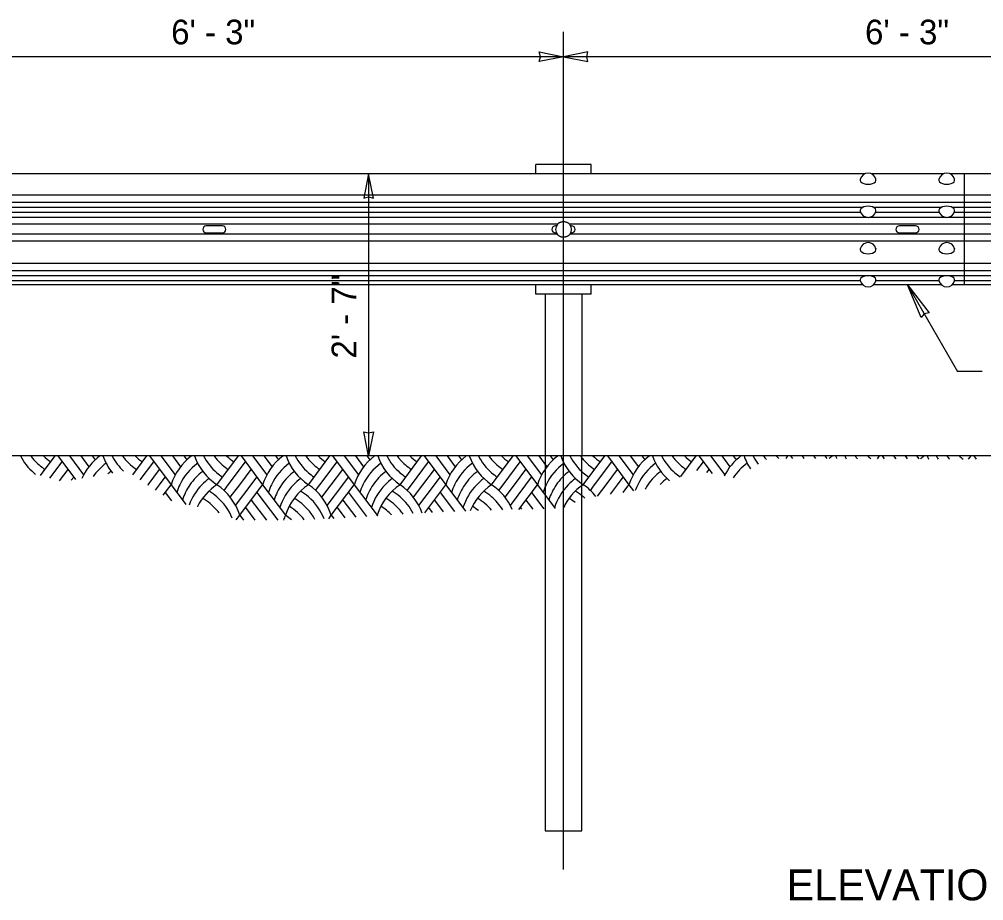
# Model space of a CAD drawing. Extents: x 99862 to 103680, y 99470 to 102076.
# Drawn here: x 100385 to 101011, y 100797 to 101369 of the extents above; entities that cross this region are included whole.
import ezdxf

# ---------------------------------------------------------------- set-up
doc = ezdxf.new("R2010")
doc.units = 0
for name, color, linetype in [('Level 14', 7, 'Continuous'), ('Level 15', 7, 'Continuous'), ('Level 2', 7, 'Continuous'), ('Level 20', 7, 'Continuous'), ('Level 27', 7, 'Continuous'), ('Level 4', 7, 'Continuous'), ('Level 7', 7, 'Continuous')]:
    doc.layers.add(name, color=color, linetype=linetype)

msp = doc.modelspace()

# ---------------------------------------------------------------- linework, layer by layer
at = {"layer": 'Level 14'}
for p, q in [((100738.31, 100817.51), (100738.31, 101360.59)), ((102045.91, 101085.68), (99896.57, 101085.68)), ((100399.07, 101072.92), (100408.63, 101085.68)), ((100405.19, 101071.19), (100413.21, 101081.88)), ((100410.36, 101085.68), (100421.83, 101070.37)), ((100417.78, 101085.68), (100427.02, 101073.36)), ((100425.21, 101085.68), (100430.46, 101078.67)), ((100432.63, 101085.68), (100434.54, 101083.13)), ((100458.87, 101073.47), (100468.03, 101085.68)), ((100463.82, 101070.17), (100472.6, 101081.88)), ((100469.75, 101085.68), (100483.74, 101067.03)), ((100477.18, 101085.68), (100486.41, 101073.36)), ((100484.6, 101085.68), (100489.86, 101078.67)), ((100492.03, 101085.68), (100493.93, 101083.13)), ((100513.44, 101067.03), (100527.42, 101085.68)), ((100520.86, 101067.03), (100532, 101081.88)), ((100529.15, 101085.68), (100543.14, 101067.03)), ((100536.57, 101085.68), (100545.81, 101073.36)), ((100544, 101085.68), (100549.25, 101078.67)), ((100551.42, 101085.68), (100553.33, 101083.13)), ((100572.83, 101067.03), (100586.82, 101085.68)), ((100580.26, 101067.03), (100591.39, 101081.88)), ((100588.54, 101085.68), (100602.53, 101067.03)), ((100595.97, 101085.68), (100605.21, 101073.36)), ((100603.39, 101085.68), (100608.65, 101078.67)), ((100610.82, 101085.68), (100612.73, 101083.13)), ((100632.23, 101067.03), (100646.22, 101085.68)), ((100639.65, 101067.03), (100650.79, 101081.88)), ((100647.94, 101085.68), (100661.93, 101067.03)), ((100655.36, 101085.68), (100664.6, 101073.36)), ((100662.79, 101085.68), (100668.05, 101078.67)), ((100670.21, 101085.68), (100672.12, 101083.13)), ((100691.62, 101067.03), (100705.61, 101085.68)), ((100699.05, 101067.03), (100710.19, 101081.88)), ((100707.34, 101085.68), (100721.32, 101067.03)), ((100714.76, 101085.68), (100724, 101073.36)), ((100722.19, 101085.68), (100727.44, 101078.67)), ((100729.61, 101085.68), (100731.52, 101083.13)), ((100751.02, 101067.03), (100765.01, 101085.68)), ((100758.45, 101067.03), (100769.58, 101081.88)), ((100766.73, 101085.68), (100780.72, 101067.03)), ((100774.16, 101085.68), (100783.39, 101073.36)), ((100781.58, 101085.68), (100786.84, 101078.67)), ((100789.01, 101085.68), (100790.91, 101083.13)), ((100814.42, 101072.36), (100824.4, 101085.68)), ((100824.78, 101076.28), (100828.98, 101081.88)), ((100826.13, 101085.68), (100834.72, 101074.23)), ((100833.55, 101085.68), (100842.79, 101073.36)), ((100840.98, 101085.68), (100846.23, 101078.67)), ((100848.4, 101085.68), (100850.31, 101083.13)), ((100882.59, 101084.07), (100883.8, 101085.68)), ((100885.52, 101085.68), (100886.74, 101084.05)), ((100892.95, 101085.68), (100894.19, 101084.02)), ((100900.37, 101085.68), (100901.64, 101084)), ((100907.8, 101085.68), (100909.08, 101083.97)), ((100941.82, 101083.84), (100943.2, 101085.68)), ((100944.92, 101085.68), (100946.31, 101083.82)), ((100952.34, 101085.68), (100953.76, 101083.8)), ((100959.77, 101085.68), (100961.2, 101083.77)), ((100967.19, 101085.68), (100968.66, 101083.73)), ((101001, 101083.55), (101002.59, 101085.68)), ((101004.32, 101085.68), (101005.93, 101083.52)), ((100411.32, 101069.46), (100416.92, 101076.93)), ((100468.89, 101067.03), (100476.31, 101076.93)), ((100528.29, 101067.03), (100535.71, 101076.93)), ((100587.68, 101067.03), (100595.11, 101076.93)), ((100647.08, 101067.03), (100654.5, 101076.93)), ((100706.47, 101067.03), (100713.9, 101076.93)), ((100765.87, 101067.03), (100773.29, 101076.93)), ((100831.21, 101074.95), (100832.69, 101076.93)), ((100419.07, 101069.9), (100420.63, 101071.98)), ((100476.31, 101067.03), (100480.03, 101071.98)), ((100535.71, 101067.03), (100539.42, 101071.98)), ((100595.11, 101067.03), (100598.82, 101071.98)), ((100654.5, 101067.03), (100658.22, 101071.98)), ((100713.9, 101067.03), (100717.61, 101071.98)), ((100773.29, 101067.03), (100777.01, 101071.98)), ((100468.77, 101066.87), (100468.89, 101067.03)), ((100473.72, 101063.57), (100476.31, 101067.03)), ((100478.67, 101060.27), (100483.74, 101067.03)), ((100483.74, 101067.03), (100493.42, 101054.12)), ((100518.09, 101063.34), (100520.86, 101067.03)), ((100522.17, 101058.87), (100528.29, 101067.03)), ((100525.61, 101053.56), (100535.71, 101067.03)), ((100528.29, 101047.23), (100543.14, 101067.03)), ((100543.14, 101067.03), (100557.98, 101047.23)), ((100577.49, 101063.34), (100580.26, 101067.03)), ((100581.56, 101058.87), (100587.68, 101067.03)), ((100585.01, 101053.56), (100595.11, 101067.03)), ((100587.68, 101047.23), (100602.53, 101067.03)), ((100602.53, 101067.03), (100617.38, 101047.23)), ((100636.88, 101063.34), (100639.65, 101067.03)), ((100640.96, 101058.87), (100647.08, 101067.03)), ((100644.4, 101053.56), (100654.5, 101067.03)), ((100648.24, 101048.78), (100661.93, 101067.03)), ((100661.93, 101067.03), (100674.71, 101049.99)), ((100696.28, 101063.34), (100699.05, 101067.03)), ((100700.36, 101058.87), (100706.47, 101067.03)), ((100703.8, 101053.56), (100713.9, 101067.03)), ((100709.36, 101051.08), (100721.32, 101067.03)), ((100721.32, 101067.03), (100732.94, 101051.55)), ((100755.68, 101063.34), (100758.45, 101067.03)), ((100760.31, 101059.62), (100765.87, 101067.03)), ((100768.66, 101060.85), (100773.29, 101067.03)), ((100777, 101062.07), (100780.72, 101067.03)), ((100780.72, 101067.03), (100783.7, 101063.06)), ((100480.03, 101062.08), (100484.1, 101056.65)), ((100535.71, 101057.13), (100545.55, 101044.01)), ((100539.42, 101062.08), (100552.94, 101044.05)), ((100595.11, 101057.13), (100603.52, 101045.91)), ((100598.82, 101062.08), (100610.58, 101046.4)), ((100654.5, 101057.13), (100660.32, 101049.37)), ((100658.22, 101062.08), (100667.51, 101049.69)), ((100713.9, 101057.13), (100718.28, 101051.28)), ((100717.61, 101062.08), (100725.6, 101051.42)), ((100777.01, 101062.08), (100777.01, 101062.07)), ((100532, 101052.18), (100538.12, 101044.01)), ((100591.39, 101052.18), (100596.42, 101045.48)), ((100650.79, 101052.18), (100653.15, 101049.03)), ((100710.19, 101052.18), (100710.98, 101051.12)), ((100526.06, 101044.26), (100528.29, 101047.23)), ((100528.29, 101047.23), (100530.65, 101044.08)), ((100585.97, 101044.95), (100587.68, 101047.23)), ((100587.68, 101047.23), (100589.28, 101045.1))]:
    msp.add_line(p, q, dxfattribs=at)
for centre, start, end in [((100419.32, 101103.17), 207.73613, 228.95992), ((100423.03, 101108.12), 216.66402, 220.94161), ((100423.03, 101108.12), 220.94154, 236.09639), ((100426.74, 101113.07), 226.78948, 236.09639), ((100460.15, 101055.64), 126.9281, 155.74427), ((100475, 101098.22), 199.49222, 219.07787), ((100478.71, 101103.17), 207.73613, 226.80948), ((100482.43, 101108.12), 216.66402, 220.94161), ((100482.43, 101108.12), 220.94154, 236.09639), ((100486.14, 101113.07), 226.78948, 236.09639), ((100519.55, 101055.64), 126.9281, 162.3566), ((100534.4, 101098.22), 199.49222, 236.09639), ((100538.11, 101103.17), 207.73613, 228.95992), ((100541.82, 101108.12), 216.66402, 220.94161), ((100541.82, 101108.12), 220.94154, 236.09639), ((100545.53, 101113.07), 226.78948, 236.09639), ((100578.95, 101055.64), 126.9281, 162.3566), ((100593.79, 101098.22), 199.49222, 236.09639), ((100597.51, 101103.17), 207.73613, 228.95992), ((100601.22, 101108.12), 216.66402, 220.94161), ((100601.22, 101108.12), 220.94154, 236.09639), ((100604.93, 101113.07), 226.78948, 236.09639), ((100638.34, 101055.64), 126.9281, 162.3566), ((100653.19, 101098.22), 199.49222, 236.09639), ((100656.9, 101103.17), 207.73613, 228.95992), ((100660.62, 101108.12), 216.66402, 220.94161), ((100660.61, 101108.12), 220.94154, 236.09639), ((100664.33, 101113.07), 226.78948, 236.09639), ((100697.74, 101055.64), 126.9281, 162.3566), ((100712.59, 101098.22), 199.49222, 236.09639), ((100716.3, 101103.17), 207.73613, 228.95992), ((100720.01, 101108.12), 216.66402, 220.94161), ((100720.01, 101108.12), 220.94154, 236.09639), ((100723.72, 101113.07), 226.78948, 236.09639), ((100757.13, 101055.64), 126.9281, 162.3566), ((100771.98, 101098.22), 199.49222, 236.09639), ((100775.69, 101103.17), 207.73613, 228.95992), ((100779.41, 101108.12), 216.66402, 220.94161), ((100779.41, 101108.12), 220.94154, 236.09639), ((100783.12, 101113.07), 226.78948, 236.09639), ((100816.53, 101055.64), 126.9281, 162.3566), ((100831.38, 101098.22), 199.49222, 229.66974), ((100835.09, 101103.17), 207.73613, 228.95992), ((100838.8, 101108.12), 216.66402, 220.94161), ((100838.8, 101108.12), 220.94154, 236.09639), ((100842.51, 101113.07), 226.78948, 236.09639), ((100875.93, 101055.64), 126.9281, 153.09618), ((100890.77, 101098.22), 199.49222, 213.5936), ((100894.49, 101103.17), 207.73613, 217.29235), ((100898.2, 101108.12), 216.66402, 220.94161), ((100898.2, 101108.12), 220.94154, 221.02205), ((100901.91, 101113.07), 226.78948, 230.46563), ((100935.32, 101055.64), 126.9281, 131.09148), ((100950.17, 101098.22), 199.49222, 202.32726), ((100953.88, 101103.17), 207.73613, 210.81382), ((100957.6, 101108.12), 216.66402, 220.14409), ((100961.31, 101113.07), 226.78948, 231.01683), ((100994.72, 101055.64), 126.9281, 131.63817), ((101009.57, 101098.22), 199.49222, 202.7355), ((101013.28, 101103.17), 207.73613, 211.27357), ((101016.99, 101108.12), 216.66402, 220.68748), ((101020.7, 101113.07), 226.78948, 231.71845), ((100463.87, 101050.69), 126.30625, 144.83319), ((100467.58, 101045.74), 127.1006, 131.21406), ((100523.26, 101050.69), 126.30625, 154.2266), ((100526.97, 101045.74), 127.1006, 145.49109), ((100582.66, 101050.69), 126.30625, 154.2266), ((100586.37, 101045.74), 127.1006, 145.49109), ((100642.05, 101050.69), 126.30625, 154.2266), ((100645.77, 101045.74), 127.1006, 145.49109), ((100701.45, 101050.69), 126.30625, 154.2266), ((100705.16, 101045.74), 127.1006, 145.49109), ((100760.85, 101050.69), 126.30625, 154.2266), ((100764.56, 101045.74), 127.1006, 145.49109), ((100820.24, 101050.69), 126.30625, 154.2266), ((100823.95, 101045.74), 127.1006, 145.49109), ((100879.64, 101050.69), 126.30625, 146.49969), ((100419.32, 101103.17), 228.95986, 231.30214), ((100530.69, 101040.79), 126.331, 135.71278), ((100538.11, 101103.17), 228.95986, 236.09639), ((100590.08, 101040.79), 126.331, 135.71278), ((100597.51, 101103.17), 228.95986, 236.09639), ((100649.48, 101040.79), 126.331, 135.71278), ((100656.9, 101103.17), 228.95986, 236.09639), ((100708.87, 101040.79), 126.331, 135.71278), ((100716.3, 101103.17), 228.95986, 236.09639), ((100768.27, 101040.79), 126.331, 135.71278), ((100775.69, 101103.17), 228.95986, 236.09639), ((100827.67, 101040.79), 126.331, 135.18622), ((100835.09, 101103.17), 228.95986, 235.61605), ((100523.26, 101050.69), 154.22654, 162.3566), ((100526.97, 101045.74), 145.49102, 162.3566), ((100530.69, 101040.79), 135.71269, 159.74489), ((100534.4, 101035.84), 123.90361, 152.96624), ((100488.76, 101030.89), 48.95968, 58.54646), ((100492.48, 101035.84), 17.6434, 56.09634), ((100582.66, 101050.69), 154.22654, 162.3566), ((100586.37, 101045.74), 145.49102, 162.3566), ((100590.08, 101040.79), 135.71269, 162.3566), ((100593.79, 101035.84), 123.90361, 162.3566), ((100548.16, 101030.89), 48.95968, 58.54646), ((100551.87, 101035.84), 17.6434, 56.09634), ((100642.05, 101050.69), 154.22654, 162.3566), ((100645.77, 101045.74), 145.49102, 162.3566), ((100649.48, 101040.79), 135.71269, 162.3566), ((100653.19, 101035.84), 123.90361, 162.3566), ((100607.56, 101030.89), 48.95968, 58.54646), ((100611.27, 101035.84), 19.99304, 56.09634), ((100701.45, 101050.69), 154.22654, 162.3566), ((100705.16, 101045.74), 145.49102, 162.3566), ((100708.87, 101040.79), 135.71269, 162.3566), ((100712.59, 101035.84), 123.90361, 157.69173), ((100666.95, 101030.89), 48.95968, 58.54646), ((100670.66, 101035.84), 23.744, 56.09634), ((100760.85, 101050.69), 154.22654, 162.3566), ((100764.56, 101045.74), 145.49102, 162.3566), ((100768.27, 101040.79), 135.71269, 162.3566), ((100771.98, 101035.84), 123.90361, 154.82784), ((100726.35, 101030.89), 48.95968, 58.54646), ((100730.06, 101035.84), 38.95727, 56.09634), ((100820.24, 101050.69), 154.22654, 160.52321), ((100823.95, 101045.74), 145.49102, 150.65193), ((100485.05, 101025.94), 40.94134, 59.30215), ((100488.76, 101030.89), 22.50024, 48.95975), ((100544.45, 101025.94), 40.94134, 59.30215), ((100548.16, 101030.89), 21.75916, 48.95975), ((100603.84, 101025.94), 40.94134, 59.30215), ((100607.56, 101030.89), 27.72462, 48.95975), ((100663.24, 101025.94), 40.94134, 59.30215), ((100666.95, 101030.89), 31.99409, 48.95975), ((100722.64, 101025.94), 51.71499, 59.30215), ((100726.35, 101030.89), 46.72757, 48.95975), ((100481.34, 101020.99), 58.03494, 58.48737), ((100485.05, 101025.94), 37.06672, 40.94141), ((100540.74, 101020.99), 38.47952, 58.48737), ((100544.45, 101025.94), 29.75553, 40.94141), ((100600.13, 101020.99), 44.91449, 58.48737), ((100603.84, 101025.94), 35.93022, 40.94141), ((100659.53, 101020.99), 51.24667, 58.48737), ((100718.92, 101020.99), 56.93696, 58.48737), ((100522.17, 101058.62), 337.26527, 342.3566), ((100537.02, 101016.04), 48.48967, 56.09639), ((100581.57, 101058.62), 341.80373, 342.3566), ((100596.42, 101016.04), 55.26937, 56.09639)]:
    msp.add_arc(centre, 37.58, start, end, dxfattribs=at)
at = {"layer": 'Level 15'}
for p, q in [((100738.31, 101344.59), (100288.31, 101344.59)), ((101188.31, 101344.59), (100738.31, 101344.59)), ((100611.87, 101268.68), (100611.87, 101085.68)), ((100961.33, 101196.69), (100993.83, 101140.4)), ((101009.83, 101140.4), (100993.83, 101140.4))]:
    msp.add_line(p, q, dxfattribs=at)
for points in [[(100738.31, 101344.59), (100722.58, 101341.51), (100723.31, 101344.59), (100722.58, 101347.68)], [(100738.31, 101344.59), (100754.03, 101341.51), (100753.31, 101344.59), (100754.03, 101347.68)], [(100611.87, 101268.68), (100608.79, 101252.95), (100611.87, 101253.68), (100614.96, 101252.95)], [(100961.33, 101196.69), (100975.33, 101178.41), (100972.22, 101177.83), (100970.16, 101175.42)], [(100611.87, 101085.68), (100608.79, 101101.4), (100611.87, 101100.68), (100614.96, 101101.4)]]:
    msp.add_lwpolyline(points, close=True, dxfattribs=at)
at = {"layer": 'Level 2'}
for p, q in [((100720.31, 101268.5), (100720.31, 101274.59)), ((100756.31, 101274.59), (100720.31, 101274.59)), ((100756.31, 101268.5), (100756.31, 101274.59)), ((100720.31, 101190.59), (100720.31, 101196.69)), ((100756.31, 101190.59), (100756.31, 101196.69)), ((100756.31, 101190.59), (100720.31, 101190.59))]:
    msp.add_line(p, q, dxfattribs=at)
at = {"layer": 'Level 27'}
for p, q in [((100933.93, 101268.68), (100089.21, 101268.68)), ((100984.93, 101268.68), (100937.73, 101268.68)), ((101833.93, 101268.68), (100988.73, 101268.68)), ((100998.35, 101196.69), (100998.35, 101268.68)), ((102061.41, 101254.83), (99896.57, 101254.83)), ((102058.94, 101250.08), (99899.11, 101250.08)), ((100932.38, 101246.86), (100090.76, 101246.86)), ((100983.38, 101246.86), (100939.28, 101246.86)), ((101832.38, 101246.86), (100990.28, 101246.86)), ((100935.35, 101240.4), (100087.79, 101240.4)), ((100930.96, 101243.63), (100092.18, 101243.63)), ((100986.35, 101240.4), (100936.31, 101240.4)), ((100981.96, 101243.63), (100940.7, 101243.63)), ((101835.35, 101240.4), (100987.31, 101240.4)), ((101830.96, 101243.63), (100991.7, 101243.63)), ((100734.37, 101235.95), (100292.26, 101235.95)), ((101184.36, 101235.95), (100742.18, 101235.95)), ((100734.22, 101229.41), (100292.42, 101229.41)), ((101184.21, 101229.41), (100742.33, 101229.41)), ((102045.2, 101224.96), (99913.17, 101224.96)), ((102061.41, 101210.53), (99896.57, 101210.53)), ((102058.94, 101205.78), (99899.11, 101205.78)), ((100935.23, 101202.56), (100087.91, 101202.56)), ((100986.23, 101202.56), (100936.43, 101202.56)), ((101835.23, 101202.56), (100987.43, 101202.56)), ((100932.34, 101196.69), (100090.8, 101196.69)), ((100930.72, 101199.33), (100092.42, 101199.33)), ((100983.34, 101196.69), (100939.33, 101196.69)), ((100981.72, 101199.33), (100940.94, 101199.33)), ((101832.34, 101196.69), (100990.33, 101196.69)), ((101830.72, 101199.33), (100991.94, 101199.33))]:
    msp.add_line(p, q, dxfattribs=at)
at = {"layer": 'Level 4'}
for p, q in [((100726.45, 101190.59), (100726.45, 101085.68)), ((100750.09, 101190.59), (100750.09, 101085.68)), ((100726.45, 101085.68), (100726.45, 100842.59)), ((100750.09, 100842.59), (100750.09, 101085.68)), ((100726.45, 100842.59), (100750.09, 100842.59))]:
    msp.add_line(p, q, dxfattribs=at)
at = {"layer": 'Level 7'}
for p, q in [((100940.93, 101265.12), (100940.93, 101265.12)), ((100991.93, 101265.12), (100991.93, 101265.12)), ((100517.06, 101234.84), (100506.56, 101234.84)), ((100733.64, 101234.84), (100733.02, 101234.84)), ((100742.91, 101234.84), (100743.52, 101234.84)), ((100966.58, 101234.84), (100956.08, 101234.84)), ((100506.56, 101230.34), (100517.06, 101230.34)), ((100733.02, 101230.34), (100733.64, 101230.34)), ((100743.52, 101230.34), (100742.91, 101230.34)), ((100956.08, 101230.34), (100966.58, 101230.34)), ((100940.92, 101220.1), (100940.93, 101220.09)), ((100991.92, 101220.1), (100991.93, 101220.09))]:
    msp.add_line(p, q, dxfattribs=at)
for centre, radius, start, end in [((100935.83, 101263.76), 5.27, 14.92454, 165.07546), ((100986.83, 101263.76), 5.27, 14.92454, 165.07546), ((100935.83, 101245.66), 5.27, 194.92454, 345.07546), ((100986.83, 101245.66), 5.27, 194.92454, 345.07546), ((100506.56, 101232.59), 2.25, 90, 270), ((100517.06, 101232.59), 2.25, 270, 90), ((100733.02, 101232.59), 2.25, 90, 270), ((100738.27, 101232.59), 5.15, 220.0843, 220.0843), ((100738.27, 101232.59), 5.15, 140.98001, 219.01876), ((100738.27, 101232.59), 5.15, 40.08819, 40.08867), ((100738.27, 101232.59), 5.15, 320.98653, 39.01993), ((100743.52, 101232.59), 2.25, 270, 90), ((100956.08, 101232.59), 2.25, 90, 270), ((100966.58, 101232.59), 2.25, 270, 90), ((100935.83, 101218.74), 5.27, 14.92454, 165.07546), ((100986.83, 101218.74), 5.27, 14.92454, 165.07546), ((100935.83, 101200.64), 5.27, 194.92454, 345.07546), ((100986.83, 101200.64), 5.27, 194.92454, 345.07546), ((100986.83, 101200.64), 5.27, 194.92454, 345.07546)]:
    msp.add_arc(centre, radius, start, end, dxfattribs=at)
for centre, major_axis, ratio, start_param, end_param in [((100935.83, 101264.7), (5.15, 0), 0.558353, 2.993365, 6.431413), ((100986.83, 101264.7), (5.15, 0), 0.558353, 2.993365, 6.431413), ((100935.83, 101244.72), (-5.15, 0), 0.558352, 2.993855, 6.430923), ((100986.83, 101244.72), (-5.15, 0), 0.558352, 2.993855, 6.430923), ((100935.83, 101219.67), (-5.15, 0), 0.558352, 6.132899, 9.575065), ((100986.83, 101219.67), (-5.15, 0), 0.558352, 6.132899, 9.575065), ((100935.83, 101199.7), (-5.15, 0), 0.558352, 2.993855, 6.430923), ((100986.83, 101199.7), (-5.15, 0), 0.558352, 2.993855, 6.430923), ((100986.83, 101199.7), (-5.15, 0), 0.558352, 2.993855, 6.430923)]:
    msp.add_ellipse(centre, major_axis=major_axis, ratio=ratio, start_param=start_param, end_param=end_param, dxfattribs=at)
for points in [[(100734.27, 101235.83), (100734.61, 101236.25), (100735.03, 101236.62), (100735.49, 101236.9), (100735.95, 101237.18), (100736.46, 101237.39), (100736.98, 101237.51), (100737.54, 101237.65), (100738.14, 101237.69), (100738.72, 101237.65), (100739.3, 101237.6), (100739.89, 101237.46), (100740.43, 101237.22), (100740.97, 101236.99), (100741.47, 101236.66), (100741.9, 101236.25), (100742.03, 101236.12), (100742.16, 101235.98), (100742.28, 101235.83)], [(100742.28, 101229.35), (100741.94, 101228.93), (100741.53, 101228.57), (100741.07, 101228.29), (100740.61, 101228.01), (100740.1, 101227.8), (100739.58, 101227.67), (100739.02, 101227.54), (100738.42, 101227.49), (100737.85, 101227.53), (100737.26, 101227.58), (100736.67, 101227.72), (100736.13, 101227.95), (100735.59, 101228.19), (100735.08, 101228.52), (100734.66, 101228.93), (100734.52, 101229.06), (100734.39, 101229.2), (100734.27, 101229.35)]]:
    msp.add_open_spline(points, degree=3, dxfattribs=at)

# ---------------------------------------------------------------- texts
at = {"layer": 'Level 20'}
for s, height, p in [('6\' - 3"', 16, (100483.83, 101352.59)), ('6\' - 3"', 16, (100933.83, 101352.59)), ('ELEVATION ', 20, (100883.02, 100797.59))]:
    msp.add_text(s, height=height, dxfattribs=at).set_placement(p)
msp.add_text('2\' - 7"', height=16, rotation=90, dxfattribs=at).set_placement((100603.87, 101148.84))

doc.saveas('drawing.dxf')
